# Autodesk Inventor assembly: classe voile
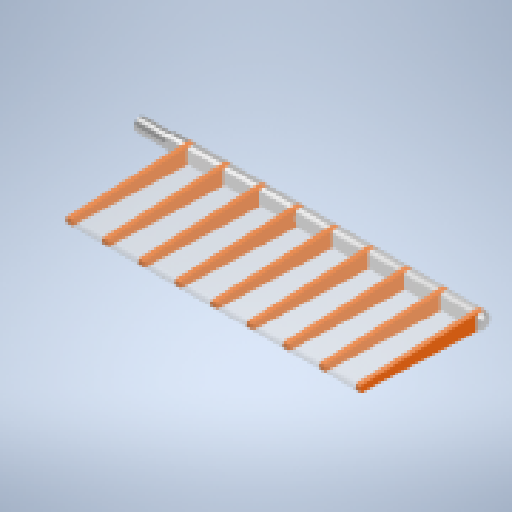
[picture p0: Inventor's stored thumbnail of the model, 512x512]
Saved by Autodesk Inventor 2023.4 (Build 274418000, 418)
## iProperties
Created: 2023-11
Part Number: classe voile
Document SubType Name: Assembly
Designer: mel
Author: mel
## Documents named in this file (4)
- D:\travail\année 2023-2024\IT\char à voile\classe voile.iam
- D:\travail\année 2023-2024\IT\char à voile\axe voile.ipt
- D:\travail\année 2023-2024\IT\char à voile\hauban.ipt
- D:\travail\année 2023-2024\IT\char à voile\voile.ipt
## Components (11 placed, 3 different names)
1. axe voile:1 — Affleurement:1
2. voile:1 — Affleurement:2
3. hauban:1 — Affleurement:1
4. hauban:2
5. hauban:3
6. hauban:4
7. hauban:5
8. hauban:6
9. hauban:7
10. hauban:8
11. hauban:9 — Affleurement:2
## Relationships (2: Flush 2)
- Affleurement:1 [Flush]: axe voile:1 ↔ hauban:1
- Affleurement:2 [Flush]: voile:1 ↔ hauban:9
